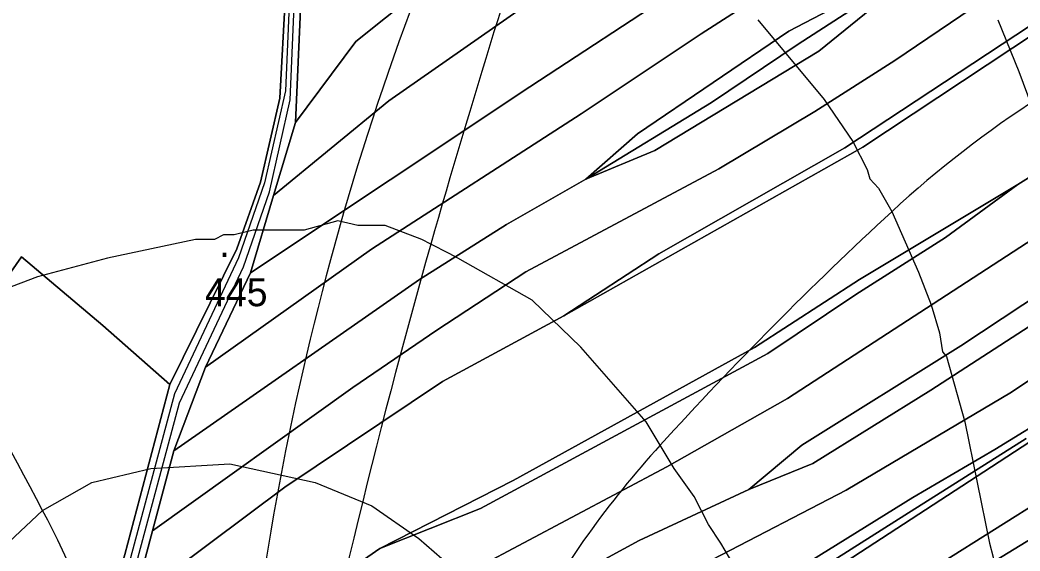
# Model space of a CAD drawing. Extents: x -510989 to -501240, y -1184665 to -1176089.
# Drawn here: x -504125.8 to -503911.8, y -1182692.7 to -1182579 of the extents above; entities that cross this region are included whole.
import ezdxf

# ---------------------------------------------------------------- set-up
doc = ezdxf.new("R2010")
doc.units = 0
for name, color, linetype in [('lesni_pozemek', 7, 'Continuous'), ('NAVRH_rozvodnice', 7, 'Continuous'), ('ostatni_plocha_x_ostatni_komunikace', 7, 'Continuous'), ('popis', 7, 'Continuous'), ('STAV_povodi', 7, 'Continuous'), ('STAV_zaplavove_uzemi', 7, 'Continuous'), ('trvaly_travni_porost', 7, 'Continuous'), ('vrstevnice_01', 7, 'Continuous'), ('vrstevnice_02', 7, 'Continuous'), ('vrstevnice_05', 7, 'Continuous')]:
    doc.layers.add(name, color=color, linetype=linetype)

msp = doc.modelspace()

# ---------------------------------------------------------------- linework, layer by layer
at = {"layer": 'lesni_pozemek'}
for points in [[(-504087.39, -1182187.43), (-504067.44, -1182225.52), (-504061.18, -1182261.91), (-504049.87, -1182293.37), (-504048.75, -1182293.45), (-504047.69, -1182317.73), (-504054.51, -1182368.02), (-504079.47, -1182472.68), (-504067.83, -1182551.12), (-504070.26, -1182595.76), (-504074.34, -1182613.7), (-504079.45, -1182627.96), (-504093.8, -1182657.06), (-504108.08, -1182644.43), (-504125.54, -1182629.68), (-504155.94, -1182673.32)], [(-503826.28, -1182450.37), (-503842.36, -1182456.45), (-503879.91, -1182462.45), (-503920.77, -1182491.62), (-503933.06, -1182502.22), (-503948.85, -1182515.4), (-503964.92, -1182524.71), (-503973.4, -1182530.06), (-504022.57, -1182558.48), (-504053.96, -1182583.64), (-504066.88, -1182600.91), (-504064.75, -1182552.42), (-504067.76, -1182532.83), (-504075.7, -1182475.14), (-504051.84, -1182373.59)]]:
    msp.add_lwpolyline(points, dxfattribs=at)
for points in [[(-503933.06, -1182502.22), (-503925.87, -1182512.32), (-503923.58, -1182516.11), (-503935.22, -1182524.39), (-503963.01, -1182541.37), (-504014.78, -1182573.82), (-504046.92, -1182596.31), (-504071.56, -1182616.57), (-504066.88, -1182600.91), (-504053.96, -1182583.64), (-504022.57, -1182558.48), (-503973.4, -1182530.06), (-503964.92, -1182524.71), (-503948.85, -1182515.4)], [(-503923.58, -1182516.11), (-503915.17, -1182528.48), (-503985.13, -1182572.56), (-504016.71, -1182593.3), (-504076.52, -1182633.12), (-504071.56, -1182616.57), (-504046.92, -1182596.31), (-504014.78, -1182573.82), (-503963.01, -1182541.37), (-503935.22, -1182524.39)], [(-504108.08, -1182644.43), (-504093.8, -1182657.06), (-504103.38, -1182693.45), (-504117.63, -1182740.83), (-504118.68, -1182746.36), (-504132.13, -1182733.89), (-504174.32, -1182695.83), (-504155.94, -1182673.32), (-504125.54, -1182629.68)]]:
    msp.add_lwpolyline(points, close=True, dxfattribs=at)
at = {"layer": 'NAVRH_rozvodnice'}
for centre, radius, start, end in [((-509825.79, -1185728.25), 6466.23, 28.085774, 29.710253), ((-502263.51, -1183130.33), 1844.4, 161.21831, 164.16335), ((-503782.29, -1182790.21), 231.49, 112.9221, 132.6689), ((-503401.93, -1183202.85), 792.69, 132.6689, 137.76243), ((-502469.97, -1183071.76), 1629.8, 164.16335, 168.739), ((-503830.02, -1182814.17), 214.47, 137.7624, 150.9414), ((-504282.44, -1182770.15), 182.99, 4.4346, 28.0858)]:
    msp.add_arc(centre, radius, start, end, dxfattribs=at)
at = {"layer": 'ostatni_plocha_x_ostatni_komunikace'}
for points in [[(-504054.06, -1182368.12), (-504078.54, -1182472.67), (-504067.18, -1182550.64), (-504069.04, -1182594.17), (-504073.53, -1182613.89), (-504079.06, -1182629.93), (-504092.77, -1182658.99), (-504113.17, -1182735.06), (-504118.8, -1182751), (-504120.13, -1182748.75), (-504118.68, -1182746.36), (-504117.63, -1182740.83), (-504103.38, -1182693.45), (-504093.8, -1182657.06), (-504079.45, -1182627.96), (-504074.34, -1182613.7), (-504070.26, -1182595.76), (-504067.83, -1182551.12), (-504079.47, -1182472.68), (-504054.51, -1182368.02)], [(-504064.75, -1182552.42), (-504066.88, -1182600.91), (-504071.56, -1182616.57), (-504076.52, -1182633.12), (-504086.12, -1182653.29), (-504092.94, -1182671.23), (-504097.49, -1182688.34), (-504101.43, -1182703.13), (-504106.25, -1182722.37), (-504111.13, -1182738.96), (-504117.35, -1182757.54), (-504118.17, -1182760.19), (-504119.38, -1182757.61), (-504112.1, -1182737), (-504091.71, -1182660.92), (-504078, -1182631.85), (-504072.47, -1182615.81), (-504067.98, -1182596.08), (-504066.13, -1182552.55)]]:
    msp.add_lwpolyline(points, dxfattribs=at)
at = {"layer": 'popis'}
msp.add_lwpolyline([(-504056.26, -1182843.61), (-504081.89, -1182809.86), (-504088.59, -1182804.23), (-504111.83, -1182773.79), (-504119.38, -1182757.61), (-504115.74, -1182747.3), (-504101.91, -1182698.96), (-504091.71, -1182660.92), (-504078, -1182631.85), (-504072.47, -1182615.81), (-504067.98, -1182596.08), (-504066.13, -1182552.55), (-504077.49, -1182474.57), (-504065.26, -1182422.28), (-504053.02, -1182369.99), (-504046.18, -1182319.23), (-504047.14, -1182295.34), (-504048.85, -1182295.22), (-504060.16, -1182263.76), (-504066.42, -1182227.36), (-504086.38, -1182189.26)], dxfattribs=at)
at = {"layer": 'STAV_povodi'}
msp.add_arc((-503464.96, -1182791.43), 615.87, 155.3948, 176.23631, dxfattribs=at)
at = {"layer": 'STAV_zaplavove_uzemi'}
msp.add_spline([(-502250.32, -1184002.61), (-502355.07, -1183875.41), (-502442.37, -1183790.61), (-502477.29, -1183700.82), (-502532.16, -1183578.61), (-502567.08, -1183448.91), (-502626.05, -1183402.34), (-502705.41, -1183380.59), (-502814.2, -1183349.87), (-502882.03, -1183297.39), (-502931.95, -1183237.24), (-503042.02, -1183107.97), (-503139.64, -1183018.94), (-503222.14, -1182957.59), (-503308.56, -1182839.96), (-503316.24, -1182784.92), (-503330.32, -1182756.77), (-503348.24, -1182719.65), (-503334.16, -1182651.82), (-503323.92, -1182595.5), (-503313.68, -1182526.39), (-503294.1, -1182480.5), (-503251.86, -1182396.03), (-503229.34, -1182314.37), (-503216.1, -1182227.15), (-503242.43, -1182174.5), (-503271.86, -1182129.59), (-503287.34, -1182081.58), (-503343.88, -1182028.1), (-503361.79, -1182008.91), (-503396.35, -1181952.59), (-503442.43, -1181933.39), (-503497.46, -1181888.6), (-503525.62, -1181860.44), (-503528.18, -1181837.4), (-503548.66, -1181767.01), (-503558.9, -1181729.89), (-503576.82, -1181682.53), (-503578.1, -1181621.1), (-503567.86, -1181572.46), (-503552.5, -1181536.63), (-503538.04, -1181458.36), (-503518.33, -1181411.9), (-503509.88, -1181341.51), (-503497.21, -1181207.63), (-503499.77, -1181097.56), (-503498.02, -1181031.35), (-503510.82, -1180970.85), (-503549.22, -1180952.23), (-503571.32, -1180940.6), (-503605.07, -1180937.11), (-503651.61, -1180939.44), (-503671.39, -1180917.33), (-503679.53, -1180892.89), (-503713.27, -1180871.95), (-503727.24, -1180859.15), (-503734.22, -1180833.55), (-503728.4, -1180799.81), (-503741.2, -1180770.72), (-503722.82, -1180725.17), (-503721.54, -1180703.41), (-503731.78, -1180697.01), (-503767.61, -1180699.57), (-503790.65, -1180697.01), (-503817.53, -1180697.01), (-503861.04, -1180686.77), (-503889.2, -1180675.25), (-503900.72, -1180668.85), (-503953.2, -1180679.09), (-503997.99, -1180697.01), (-504063.27, -1180722.61), (-504109.34, -1180749.49), (-504142.62, -1180776.36), (-504177.18, -1180796.84), (-504211.73, -1180817.32), (-504414.98, -1180961.5), (-504472.7, -1180998.11), (-504544.51, -1181068.5), (-504600.82, -1181143.12), (-504621.94, -1181196.62), (-504641.65, -1181267.01), (-504660.25, -1181350.62), (-504634.7, -1181398.32), (-504617.66, -1181447.72), (-504600.62, -1181492.01), (-504587, -1181548.23), (-504592.11, -1181628.29), (-504569.96, -1181682.81), (-504568.26, -1181664.07), (-504554.63, -1181621.48), (-504547.82, -1181597.63)], degree=3, dxfattribs=at)
at = {"layer": 'trvaly_travni_porost'}
for points in [[(-503768.27, -1182438.56), (-503768.5, -1182440.37), (-503769.62, -1182449.35), (-503770.06, -1182452.87), (-503779.67, -1182460.02), (-503793.67, -1182470.44), (-503818.37, -1182484.94), (-503847.32, -1182502.61), (-503884, -1182522.27), (-503906.63, -1182536.19), (-503966.89, -1182573.47), (-503980.01, -1182581.96), (-504005.71, -1182599.08), (-504050.6, -1182628.06), (-504086.12, -1182653.29), (-504076.52, -1182633.12), (-504016.71, -1182593.3), (-503985.13, -1182572.56), (-503915.17, -1182528.48), (-503859.79, -1182496.95), (-503835.26, -1182484.39), (-503797.15, -1182460.25)], [(-503774.22, -1182482.21), (-503774.74, -1182490.02), (-503775.12, -1182497.76), (-503813.01, -1182519.62), (-503844.79, -1182538.7), (-503872.94, -1182555.96), (-503949.28, -1182606.39), (-503989.12, -1182629.03), (-504009.4, -1182642.33), (-504035.41, -1182656.41), (-504069.12, -1182679.02), (-504101.43, -1182703.13), (-504097.49, -1182688.34), (-504054.63, -1182657.64), (-504036.59, -1182645.38), (-504017.6, -1182632.91), (-503976.28, -1182610.86), (-503955.72, -1182598.6), (-503938.59, -1182587.67), (-503912.52, -1182570), (-503873.08, -1182544.64), (-503841.73, -1182525.8), (-503824.87, -1182515.87)], [(-503775.12, -1182497.76), (-503775.27, -1182500.79), (-503813.1, -1182522.55), (-503856.21, -1182548.11), (-503887.07, -1182568.56), (-503908.01, -1182581.44), (-503945.44, -1182606.2), (-504009.4, -1182642.33), (-503989.12, -1182629.03), (-503949.28, -1182606.39), (-503872.94, -1182555.96), (-503844.79, -1182538.7), (-503813.01, -1182519.62)], [(-503961.3, -1182581.38), (-503928.49, -1182564.25), (-503959.3, -1182584.17), (-503977.84, -1182596.64), (-504004.75, -1182613.04), (-503993.65, -1182603.36)], [(-503928.49, -1182564.25), (-503954.84, -1182585.66), (-503989.96, -1182606.96), (-504004.75, -1182613.04), (-503977.84, -1182596.64), (-503959.3, -1182584.17)], [(-503827.85, -1182587.69), (-503834.2, -1182592.69), (-503858.37, -1182610.31), (-503877.65, -1182623.78), (-503930.87, -1182658.22), (-503956.13, -1182673.94), (-503969.82, -1182679.51), (-503958.46, -1182670.03), (-503924.47, -1182648.76), (-503866.95, -1182610.74), (-503831.53, -1182587.97), (-503817.93, -1182579.87)], [(-503812.56, -1182589.86), (-503846.15, -1182613.53), (-503870.96, -1182630.11), (-503913.58, -1182658.64), (-503948.97, -1182679.67), (-503977.58, -1182694.47), (-504020.12, -1182717.04), (-504042.97, -1182729.88), (-504070.41, -1182747.5), (-504108.65, -1182775.95), (-504111.18, -1182764.8), (-504103.68, -1182758.67), (-504076.37, -1182738.86), (-504046.46, -1182719.29), (-503993.33, -1182690.45), (-503969.82, -1182679.51), (-503956.13, -1182673.94), (-503930.87, -1182658.22), (-503877.65, -1182623.78), (-503858.37, -1182610.31), (-503834.2, -1182592.69), (-503827.85, -1182587.69)], [(-503799.62, -1182591.93), (-503819.63, -1182604.75), (-503841.89, -1182620.72), (-503879.09, -1182646.41), (-503903.66, -1182662.68), (-503917.15, -1182670.93), (-503934.74, -1182681.21), (-503970.8, -1182703.62), (-504009.81, -1182723.27), (-504066.98, -1182756.76), (-504095.54, -1182780.48), (-504101.93, -1182784.31), (-504108.65, -1182775.95), (-504070.41, -1182747.5), (-504042.97, -1182729.88), (-504020.12, -1182717.04), (-503977.58, -1182694.47), (-503948.97, -1182679.67), (-503913.58, -1182658.64), (-503870.96, -1182630.11), (-503846.15, -1182613.53), (-503812.56, -1182589.86)], [(-503927.75, -1182625.59), (-503946.95, -1182637.74), (-503965.78, -1182650.36), (-504027.29, -1182683.57), (-504048.84, -1182692.16), (-504020.3, -1182677.6), (-503968.65, -1182649.1), (-503946.13, -1182634.57), (-503912.24, -1182614.23)]]:
    msp.add_lwpolyline(points, close=True, dxfattribs=at)
for points in [[(-503911.33, -1182553.61), (-503928.49, -1182564.25), (-503961.3, -1182581.38), (-503993.65, -1182603.36), (-504004.75, -1182613.04), (-504021.69, -1182622.77), (-504040.33, -1182634.53), (-504092.94, -1182671.23), (-504086.12, -1182653.29), (-504050.6, -1182628.06), (-504005.71, -1182599.08), (-503980.01, -1182581.96), (-503966.89, -1182573.47), (-503906.63, -1182536.19)], [(-503873.08, -1182544.64), (-503912.52, -1182570), (-503938.59, -1182587.67), (-503955.72, -1182598.6), (-503976.28, -1182610.86), (-504017.6, -1182632.91), (-504036.59, -1182645.38), (-504054.63, -1182657.64), (-504097.49, -1182688.34), (-504092.94, -1182671.23), (-504040.33, -1182634.53), (-504021.69, -1182622.77), (-504004.75, -1182613.04), (-503989.96, -1182606.96), (-503954.84, -1182585.66), (-503928.49, -1182564.25), (-503911.33, -1182553.61)], [(-503891.87, -1182601.48), (-503912.24, -1182614.23), (-503946.13, -1182634.57), (-503968.65, -1182649.1), (-504020.3, -1182677.6), (-504048.84, -1182692.16), (-504077.09, -1182711.76), (-504088.29, -1182720.25), (-504111.13, -1182738.96), (-504106.25, -1182722.37), (-504101.43, -1182703.13), (-504069.12, -1182679.02), (-504035.41, -1182656.41), (-504009.4, -1182642.33), (-503945.44, -1182606.2), (-503908.01, -1182581.44)], [(-503906.08, -1182624), (-503961.54, -1182660.03), (-503987.36, -1182674.64), (-504048.61, -1182707.16), (-504078.8, -1182727.06), (-504117.35, -1182757.54), (-504111.13, -1182738.96), (-504088.29, -1182720.25), (-504077.09, -1182711.76), (-504048.84, -1182692.16), (-504027.29, -1182683.57), (-503965.78, -1182650.36), (-503946.95, -1182637.74), (-503927.75, -1182625.59), (-503912.24, -1182614.23), (-503891.87, -1182601.48)], [(-503866.95, -1182610.74), (-503924.47, -1182648.76), (-503958.46, -1182670.03), (-503969.82, -1182679.51), (-503993.33, -1182690.45), (-504046.46, -1182719.29), (-504076.37, -1182738.86), (-504103.68, -1182758.67), (-504111.18, -1182764.8), (-504117.35, -1182757.54), (-504078.8, -1182727.06), (-504048.61, -1182707.16), (-503987.36, -1182674.64), (-503961.54, -1182660.03), (-503906.08, -1182624)], [(-503894.52, -1182673.81), (-503928.58, -1182695.19), (-503967.03, -1182717.56), (-504015.84, -1182742.45), (-504035.44, -1182753.78), (-504073.38, -1182775.41), (-504097.51, -1182790.06), (-504101.93, -1182784.31), (-504095.54, -1182780.48), (-504065.63, -1182762.95), (-504013.08, -1182733.53), (-503966.31, -1182709.8), (-503967.01, -1182706.74), (-503952.28, -1182697.04), (-503917.92, -1182674.63), (-503844.87, -1182627.06)], [(-503844.87, -1182627.06), (-503917.92, -1182674.63), (-503952.28, -1182697.04), (-503967.01, -1182706.74), (-503966.31, -1182709.8), (-504013.08, -1182733.53), (-504065.63, -1182762.95), (-504095.54, -1182780.48), (-504064.14, -1182758.43), (-504029.06, -1182738.71), (-504007.53, -1182726.34), (-503972.71, -1182709.17), (-503967.43, -1182704.65), (-503936.46, -1182684.98), (-503910.44, -1182668.59)], [(-503910.44, -1182668.59), (-503936.46, -1182684.98), (-503967.43, -1182704.65), (-503972.71, -1182709.17), (-504007.53, -1182726.34), (-504029.06, -1182738.71), (-504064.14, -1182758.43), (-504095.54, -1182780.48), (-504066.98, -1182756.76), (-504009.81, -1182723.27), (-503970.8, -1182703.62), (-503934.74, -1182681.21), (-503917.15, -1182670.93), (-503903.66, -1182662.68)], [(-503904.96, -1182687.38), (-503933.39, -1182704.7), (-503961.6, -1182721.14), (-503995.37, -1182738.6), (-504020.63, -1182752.44), (-504033.37, -1182759.91), (-504093.55, -1182795.2), (-504097.51, -1182790.06), (-504073.38, -1182775.41), (-504035.44, -1182753.78), (-504015.84, -1182742.45), (-503967.03, -1182717.56), (-503928.58, -1182695.19), (-503894.52, -1182673.81)], [(-503890.52, -1182687.1), (-503931.08, -1182713.41), (-503952.31, -1182724.96), (-504006.38, -1182750.87), (-504059.05, -1182782.15), (-504090.31, -1182799.54), (-504093.55, -1182795.2), (-504033.37, -1182759.91), (-504020.63, -1182752.44), (-503995.37, -1182738.6), (-503961.6, -1182721.14), (-503933.39, -1182704.7), (-503904.96, -1182687.38)]]:
    msp.add_lwpolyline(points, dxfattribs=at)
at = {"layer": 'vrstevnice_01'}
for points in [[(-503967.91, -1182579), (-503953.69, -1182596), (-503947.59, -1182605), (-503944.5, -1182611), (-503943.91, -1182613), (-503942.09, -1182615), (-503939.19, -1182620), (-503933.5, -1182633), (-503930.81, -1182640), (-503929, -1182646), (-503928.41, -1182650), (-503927.5, -1182651), (-503923.59, -1182665), (-503918.31, -1182691)], [(-504204.41, -1182834), (-504192.41, -1182801), (-504186.91, -1182777), (-504182.59, -1182765), (-504176.19, -1182751), (-504141.31, -1182703), (-504121, -1182684), (-504110.5, -1182678), (-504097.81, -1182675), (-504080.91, -1182674), (-504062.69, -1182678), (-504050.5, -1182683), (-504040.5, -1182690), (-504017.5, -1182710), (-504003.09, -1182729), (-503992.41, -1182745), (-503979.41, -1182774), (-503975.41, -1182787), (-503974.09, -1182803), (-503975.41, -1182848)], [(-503918.31, -1182691), (-503917.5, -1182694), (-503917.69, -1182696), (-503916.5, -1182700), (-503916.69, -1182702), (-503914.59, -1182722), (-503915, -1182739), (-503914.59, -1182743), (-503915.81, -1182756), (-503917.69, -1182769), (-503918.81, -1182773), (-503919.09, -1182777), (-503922.5, -1182793), (-503923, -1182799), (-503924.19, -1182803), (-503925.09, -1182811), (-503926.41, -1182815), (-503929.19, -1182841)]]:
    msp.add_lwpolyline(points, dxfattribs=at)
at = {"layer": 'vrstevnice_02'}
for points in [[(-503916.5, -1182579), (-503912, -1182590), (-503908.31, -1182600)], [(-503969.31, -1182702), (-503975.81, -1182691), (-503978.5, -1182687), (-503981.5, -1182681), (-503985.81, -1182675), (-503991.81, -1182665), (-504005.81, -1182649), (-504016.19, -1182639), (-504032.09, -1182630), (-504034, -1182629), (-504037.91, -1182627), (-504039.81, -1182626), (-504047.69, -1182623), (-504053.5, -1182623), (-504057.81, -1182622), (-504065, -1182624), (-504075.91, -1182624), (-504080, -1182625), (-504082.31, -1182625), (-504084.19, -1182626), (-504088.31, -1182626), (-504107.09, -1182630), (-504122.09, -1182634), (-504137.91, -1182640)]]:
    msp.add_lwpolyline(points, dxfattribs=at)

# ---------------------------------------------------------------- texts
at = {"layer": 'vrstevnice_05'}
for s, p in [('.', (-504083.18, -1182629.72)), ('445', (-504086.25, -1182640.27))]:
    msp.add_text(s, height=6, dxfattribs=at).set_placement(p)

doc.saveas('drawing.dxf')
